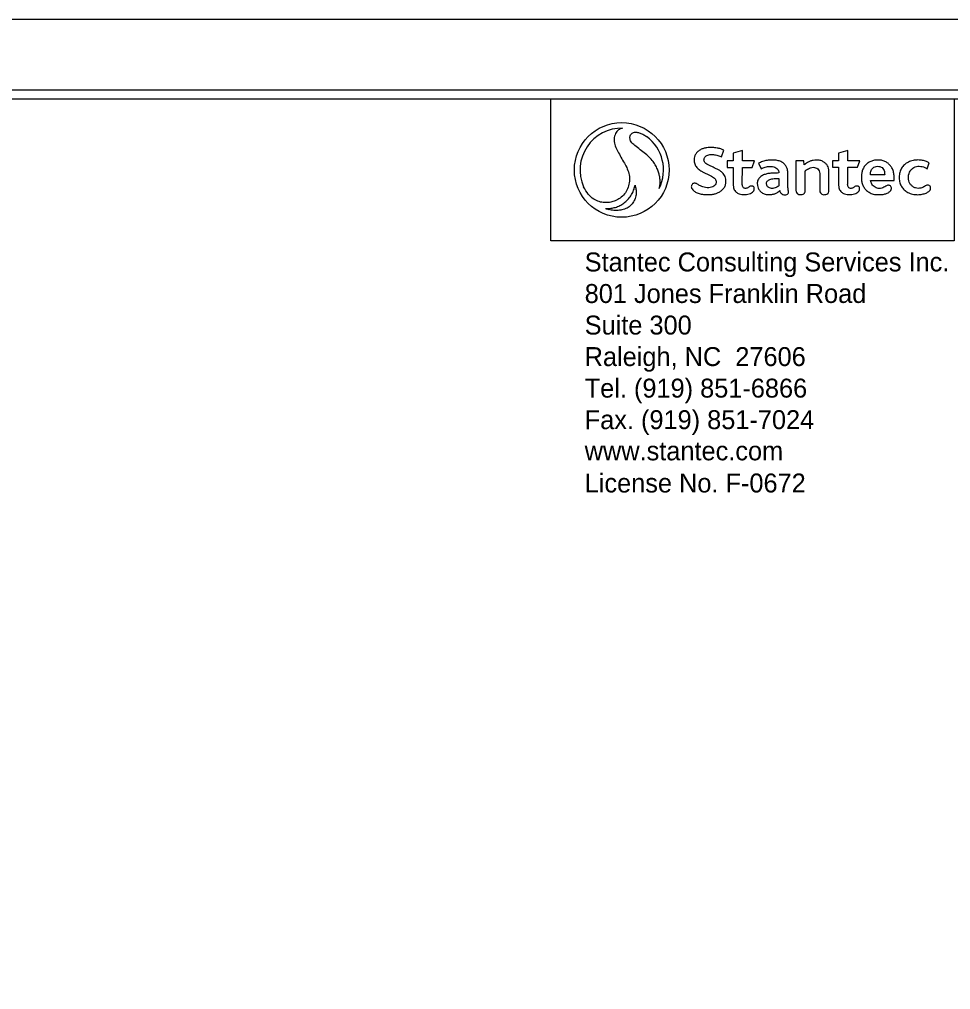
# Model space of a CAD drawing. Extents: x 2455709 to 2456046, y 594728 to 594947.
# Drawn here: x 2455949.3 to 2456001.9, y 594891.8 to 594946.6 of the extents above; entities that cross this region are included whole.
import ezdxf

# ---------------------------------------------------------------- set-up
doc = ezdxf.new("R2010")
doc.units = 0
for name, color, linetype in [('Prop Horizontal Alignment', 7, 'Continuous'), ('Prop Roadway Culvert', 7, 'Continuous'), ('Prop Vertical Profile Curve Label', 7, 'Continuous'), ('Prop Vertical Profile Grade', 7, 'Continuous'), ('Prop Vertical Profile Grade Label', 7, 'Continuous')]:
    doc.layers.add(name, color=color, linetype=linetype)

msp = doc.modelspace()

# ---------------------------------------------------------------- linework, layer by layer
at = {"layer": 'Prop Horizontal Alignment'}
msp.add_lwpolyline([(2456042.112, 594942.076), (2455742.104, 594942.076), (2455742.104, 594732.076), (2456042.107, 594732.076)], close=True, dxfattribs=at)
at = {"layer": 'Prop Roadway Culvert'}
msp.add_lwpolyline([(2455708.807, 594727.574), (2456045.507, 594727.574), (2456045.507, 594946.574), (2455708.807, 594946.574)], close=True, dxfattribs=at)
at = {"layer": 'Prop Vertical Profile Curve Label'}
msp.add_lwpolyline([(2455979.323, 594942.076), (2456002.097, 594942.079), (2456002.098, 594934.07), (2455979.324, 594934.067)], close=True, dxfattribs=at)
at = {"layer": 'Prop Vertical Profile Grade'}
msp.add_lwpolyline([(2455711.407, 594731.574), (2456044.604, 594731.576), (2456044.607, 594942.574), (2455711.407, 594942.574)], close=True, dxfattribs=at)
at = {"layer": 'Prop Vertical Profile Grade Label'}
for p, q in [((2455988.965, 594938.819), (2455989.095, 594939.192)), ((2455990.145, 594939.169), (2455989.619, 594939.022)), ((2455989.619, 594939.022), (2455989.619, 594938.585)), ((2455990.145, 594938.585), (2455990.145, 594939.169)), ((2455996.092, 594939.17), (2455995.566, 594939.023)), ((2455995.566, 594939.023), (2455995.566, 594938.586)), ((2455996.092, 594938.586), (2455996.092, 594939.17)), ((2455989.619, 594938.585), (2455989.285, 594938.585)), ((2455989.285, 594938.585), (2455989.285, 594938.219)), ((2455990.826, 594938.585), (2455990.145, 594938.585)), ((2455990.699, 594938.219), (2455990.826, 594938.585)), ((2455991.046, 594938.451), (2455991.206, 594938.141)), ((2455993.606, 594938.584), (2455993.163, 594938.584)), ((2455993.163, 594938.584), (2455993.163, 594936.906)), ((2455993.635, 594938.362), (2455993.606, 594938.584)), ((2455995.566, 594938.586), (2455995.231, 594938.586)), ((2455995.231, 594938.586), (2455995.231, 594938.22)), ((2455996.773, 594938.586), (2455996.092, 594938.586)), ((2455996.645, 594938.22), (2455996.773, 594938.586)), ((2456000.57, 594938.131), (2456000.686, 594938.475)), ((2455989.285, 594938.219), (2455989.623, 594938.219)), ((2455990.135, 594937.294), (2455990.142, 594938.219)), ((2455990.142, 594938.219), (2455990.699, 594938.219)), ((2455993.679, 594936.906), (2455993.679, 594938.014)), ((2455995.231, 594938.22), (2455995.57, 594938.22)), ((2455996.082, 594937.295), (2455996.089, 594938.22)), ((2455996.089, 594938.22), (2455996.645, 594938.22)), ((2455998.174, 594937.803), (2455997.371, 594937.803)), ((2455992.195, 594937.591), (2455992.196, 594937.176)), ((2455997.371, 594937.481), (2455998.707, 594937.481))]:
    msp.add_line(p, q, dxfattribs=at)
for points in [[(2455983.379, 594940.428), (2455983.379, 594940.428)], [(2455984.732, 594939.965), (2455984.732, 594939.965)]]:
    msp.add_lwpolyline(points, dxfattribs=at)
msp.add_circle((2455983.328, 594938.072), 2.673, dxfattribs=at)
for start, end in [(88.7738, 203.6916), (88.7673, 88.7738), (333.7886, 53.4398), (247.1256, 251.4651)]:
    msp.add_arc((2455983.328, 594938.072), 2.357, start, end, dxfattribs=at)
for points, degree in [([(2455983.379, 594940.428), (2455983.322, 594940.416), (2455983.188, 594940.388), (2455983.013, 594940.209), (2455982.883, 594939.916), (2455982.9, 594939.587), (2455983.016, 594939.269), (2455983.192, 594938.96), (2455983.374, 594938.619), (2455983.576, 594938.297), (2455983.716, 594937.97), (2455983.782, 594937.614), (2455983.739, 594937.258), (2455983.635, 594936.931), (2455983.434, 594936.634), (2455983.17, 594936.423), (2455982.894, 594936.299), (2455982.644, 594936.222), (2455982.365, 594936.222), (2455982.055, 594936.265), (2455981.749, 594936.405), (2455981.423, 594936.681), (2455981.266, 594936.952), (2455981.17, 594937.125)], 3), ([(2455983.379, 594940.428), (2455983.379, 594940.428), (2455983.379, 594940.428), (2455983.379, 594940.428)], 2), ([(2455985.442, 594937.031), (2455985.463, 594937.114), (2455985.498, 594937.269), (2455985.491, 594937.518), (2455985.467, 594937.737), (2455985.403, 594937.94), (2455985.327, 594938.175), (2455985.194, 594938.43), (2455985.004, 594938.67), (2455984.756, 594938.923), (2455984.446, 594939.148), (2455984.127, 594939.409), (2455983.871, 594939.601), (2455983.781, 594939.827), (2455983.78, 594939.999), (2455983.865, 594940.115), (2455983.978, 594940.196), (2455984.129, 594940.21), (2455984.307, 594940.176), (2455984.513, 594940.089), (2455984.655, 594940.009), (2455984.732, 594939.965)], 3), ([(2455989.095, 594939.192), (2455989.072, 594939.203), (2455988.968, 594939.253), (2455988.77, 594939.305), (2455988.527, 594939.335), (2455988.306, 594939.346), (2455988.121, 594939.328), (2455987.945, 594939.291), (2455987.775, 594939.224), (2455987.611, 594939.111), (2455987.493, 594938.961), (2455987.426, 594938.809), (2455987.411, 594938.667), (2455987.418, 594938.536), (2455987.446, 594938.411), (2455987.499, 594938.308), (2455987.563, 594938.215), (2455987.642, 594938.13), (2455987.738, 594938.053), (2455987.856, 594937.982), (2455988.003, 594937.906), (2455988.165, 594937.832), (2455988.33, 594937.762), (2455988.466, 594937.692), (2455988.566, 594937.607), (2455988.635, 594937.527), (2455988.659, 594937.429), (2455988.656, 594937.336), (2455988.618, 594937.233), (2455988.533, 594937.148), (2455988.398, 594937.09), (2455988.238, 594937.066), (2455988.06, 594937.074), (2455987.903, 594937.107), (2455987.776, 594937.17), (2455987.673, 594937.212), (2455987.604, 594937.277), (2455987.538, 594937.302), (2455987.478, 594937.328), (2455987.413, 594937.324), (2455987.348, 594937.304), (2455987.293, 594937.256), (2455987.257, 594937.188), (2455987.254, 594937.113), (2455987.265, 594937.039), (2455987.323, 594936.961), (2455987.435, 594936.849), (2455987.633, 594936.752), (2455987.878, 594936.687), (2455988.127, 594936.674), (2455988.341, 594936.68), (2455988.528, 594936.704), (2455988.692, 594936.754), (2455988.863, 594936.831), (2455989.027, 594936.96), (2455989.154, 594937.12), (2455989.208, 594937.309), (2455989.215, 594937.479), (2455989.194, 594937.633), (2455989.133, 594937.757), (2455989.06, 594937.881), (2455988.932, 594937.986), (2455988.787, 594938.083), (2455988.627, 594938.16), (2455988.454, 594938.241), (2455988.274, 594938.318), (2455988.121, 594938.399), (2455988.018, 594938.492), (2455987.974, 594938.583), (2455987.966, 594938.678), (2455987.994, 594938.765), (2455988.053, 594938.841), (2455988.135, 594938.895), (2455988.243, 594938.934), (2455988.372, 594938.944), (2455988.5, 594938.939), (2455988.627, 594938.919), (2455988.75, 594938.892), (2455988.865, 594938.858), (2455988.934, 594938.831), (2455988.965, 594938.819)], 3), ([(2455992.247, 594936.915), (2455992.248, 594936.897), (2455992.252, 594936.854), (2455992.295, 594936.79), (2455992.357, 594936.718), (2455992.469, 594936.666), (2455992.587, 594936.67), (2455992.697, 594936.694), (2455992.74, 594936.781), (2455992.742, 594936.868), (2455992.717, 594936.985), (2455992.69, 594937.307), (2455992.71, 594937.647), (2455992.704, 594938.015), (2455992.662, 594938.193), (2455992.562, 594938.353), (2455992.454, 594938.476), (2455992.276, 594938.566), (2455992.056, 594938.623), (2455991.795, 594938.64), (2455991.531, 594938.614), (2455991.277, 594938.555), (2455991.121, 594938.485), (2455991.046, 594938.451)], 3), ([(2455991.206, 594938.141), (2455991.23, 594938.154), (2455991.303, 594938.193), (2455991.422, 594938.23), (2455991.566, 594938.267), (2455991.702, 594938.276), (2455991.844, 594938.271), (2455991.972, 594938.231), (2455992.083, 594938.167), (2455992.161, 594938.074), (2455992.194, 594937.979), (2455992.194, 594937.92), (2455992.194, 594937.901)], 3), ([(2455993.679, 594938.014), (2455993.687, 594938.022), (2455993.723, 594938.055), (2455993.809, 594938.107), (2455993.921, 594938.181), (2455994.063, 594938.224), (2455994.207, 594938.223), (2455994.346, 594938.178), (2455994.441, 594938.079), (2455994.493, 594937.961), (2455994.52, 594937.801), (2455994.503, 594937.562), (2455994.515, 594937.259), (2455994.499, 594937.006), (2455994.51, 594936.832), (2455994.57, 594936.738), (2455994.675, 594936.672), (2455994.797, 594936.674), (2455994.913, 594936.702), (2455995.008, 594936.774), (2455995.035, 594936.912), (2455995.015, 594937.156), (2455995.028, 594937.456), (2455995.021, 594937.786), (2455995.033, 594937.996), (2455995.005, 594938.178), (2455994.948, 594938.306), (2455994.857, 594938.437), (2455994.711, 594938.54), (2455994.527, 594938.627), (2455994.317, 594938.632), (2455994.128, 594938.621), (2455993.958, 594938.565), (2455993.807, 594938.495), (2455993.706, 594938.415), (2455993.653, 594938.375), (2455993.635, 594938.362)], 3), ([(2455998.707, 594937.481), (2455998.709, 594937.532), (2455998.713, 594937.66), (2455998.69, 594937.866), (2455998.638, 594938.097), (2455998.527, 594938.275), (2455998.402, 594938.429), (2455998.243, 594938.538), (2455998.041, 594938.618), (2455997.815, 594938.633), (2455997.593, 594938.629), (2455997.382, 594938.562), (2455997.201, 594938.459), (2455997.044, 594938.309), (2455996.937, 594938.128), (2455996.877, 594937.929), (2455996.854, 594937.726), (2455996.851, 594937.507), (2455996.9, 594937.305), (2455996.98, 594937.108), (2455997.102, 594936.939), (2455997.288, 594936.805), (2455997.519, 594936.691), (2455997.788, 594936.677), (2455998.033, 594936.679), (2455998.241, 594936.724), (2455998.405, 594936.803), (2455998.524, 594936.907), (2455998.568, 594937.019), (2455998.548, 594937.11), (2455998.503, 594937.183), (2455998.431, 594937.203), (2455998.36, 594937.213), (2455998.278, 594937.187), (2455998.181, 594937.126), (2455998.07, 594937.059), (2455997.934, 594937.028), (2455997.808, 594937.025), (2455997.684, 594937.057), (2455997.581, 594937.128), (2455997.479, 594937.211), (2455997.419, 594937.323), (2455997.382, 594937.413), (2455997.374, 594937.464), (2455997.371, 594937.481)], 3), ([(2455997.371, 594937.803), (2455997.371, 594937.82), (2455997.371, 594937.861), (2455997.376, 594937.939), (2455997.402, 594938.04), (2455997.465, 594938.146), (2455997.562, 594938.231), (2455997.695, 594938.278), (2455997.837, 594938.282), (2455997.97, 594938.241), (2455998.083, 594938.169), (2455998.139, 594938.046), (2455998.167, 594937.922), (2455998.172, 594937.84), (2455998.174, 594937.803)], 3), ([(2456000.686, 594938.475), (2456000.642, 594938.5), (2456000.532, 594938.561), (2456000.319, 594938.617), (2456000.053, 594938.645), (2455999.77, 594938.612), (2455999.499, 594938.524), (2455999.276, 594938.374), (2455999.115, 594938.172), (2455999.015, 594937.938), (2455998.98, 594937.676), (2455999.001, 594937.411), (2455999.091, 594937.174), (2455999.225, 594936.992), (2455999.411, 594936.833), (2455999.666, 594936.714), (2455999.965, 594936.667), (2456000.239, 594936.685), (2456000.466, 594936.745), (2456000.645, 594936.827), (2456000.762, 594936.94), (2456000.768, 594937.047), (2456000.758, 594937.127), (2456000.704, 594937.176), (2456000.649, 594937.209), (2456000.588, 594937.213), (2456000.506, 594937.2), (2456000.433, 594937.136), (2456000.326, 594937.091), (2456000.22, 594937.041), (2456000.067, 594937.029), (2455999.908, 594937.043), (2455999.755, 594937.126), (2455999.64, 594937.242), (2455999.548, 594937.38), (2455999.52, 594937.544), (2455999.496, 594937.706), (2455999.542, 594937.866), (2455999.604, 594938.013), (2455999.695, 594938.13), (2455999.818, 594938.217), (2455999.958, 594938.272), (2456000.122, 594938.285), (2456000.286, 594938.27), (2456000.443, 594938.22), (2456000.529, 594938.16), (2456000.57, 594938.131)], 3), ([(2455989.623, 594938.219), (2455989.621, 594937.892), (2455989.62, 594937.547), (2455989.624, 594937.162), (2455989.641, 594937.07), (2455989.677, 594936.944), (2455989.749, 594936.858), (2455989.821, 594936.791), (2455989.898, 594936.74), (2455990.02, 594936.698), (2455990.188, 594936.679), (2455990.362, 594936.687), (2455990.536, 594936.711), (2455990.668, 594936.778), (2455990.765, 594936.856), (2455990.81, 594936.946), (2455990.815, 594937.025), (2455990.801, 594937.092), (2455990.766, 594937.131), (2455990.724, 594937.156), (2455990.675, 594937.165), (2455990.623, 594937.166), (2455990.57, 594937.152), (2455990.523, 594937.114), (2455990.47, 594937.074), (2455990.405, 594937.046), (2455990.336, 594937.024), (2455990.264, 594937.032), (2455990.202, 594937.066), (2455990.154, 594937.114), (2455990.133, 594937.197), (2455990.134, 594937.256), (2455990.135, 594937.294)], 3), ([(2455992.194, 594937.901), (2455992.16, 594937.9), (2455992.05, 594937.898), (2455991.859, 594937.889), (2455991.632, 594937.877), (2455991.42, 594937.83), (2455991.224, 594937.749), (2455991.053, 594937.602), (2455990.973, 594937.394), (2455990.984, 594937.198), (2455991.016, 594937.03), (2455991.118, 594936.888), (2455991.266, 594936.758), (2455991.478, 594936.679), (2455991.698, 594936.676), (2455991.902, 594936.702), (2455992.057, 594936.757), (2455992.172, 594936.835), (2455992.22, 594936.887), (2455992.247, 594936.915)], 3), ([(2455995.57, 594938.22), (2455995.568, 594937.892), (2455995.567, 594937.548), (2455995.57, 594937.163), (2455995.588, 594937.07), (2455995.624, 594936.944), (2455995.695, 594936.859), (2455995.768, 594936.792), (2455995.844, 594936.741), (2455995.967, 594936.698), (2455996.135, 594936.68), (2455996.309, 594936.687), (2455996.482, 594936.711), (2455996.614, 594936.778), (2455996.711, 594936.857), (2455996.757, 594936.947), (2455996.762, 594937.026), (2455996.747, 594937.092), (2455996.712, 594937.132), (2455996.671, 594937.156), (2455996.621, 594937.165), (2455996.569, 594937.166), (2455996.517, 594937.153), (2455996.47, 594937.115), (2455996.417, 594937.075), (2455996.351, 594937.047), (2455996.282, 594937.025), (2455996.211, 594937.033), (2455996.149, 594937.067), (2455996.1, 594937.115), (2455996.08, 594937.198), (2455996.081, 594937.257), (2455996.082, 594937.295)], 3), ([(2455982.412, 594935.901), (2455982.47, 594935.895), (2455982.606, 594935.882), (2455982.84, 594935.927), (2455983.101, 594935.988), (2455983.336, 594936.125), (2455983.552, 594936.277), (2455983.755, 594936.495), (2455983.923, 594936.737), (2455984.03, 594936.99), (2455984.062, 594937.139), (2455984.078, 594937.21)], 3), ([(2455984.078, 594937.21), (2455984.095, 594937.15), (2455984.139, 594936.997), (2455984.15, 594936.741), (2455984.106, 594936.463), (2455983.963, 594936.211), (2455983.771, 594935.979), (2455983.491, 594935.852), (2455983.194, 594935.784), (2455982.888, 594935.779), (2455982.679, 594935.819), (2455982.579, 594935.838)], 3), ([(2455992.196, 594937.176), (2455992.183, 594937.165), (2455992.134, 594937.128), (2455992.045, 594937.08), (2455991.92, 594937.028), (2455991.787, 594937.02), (2455991.672, 594937.05), (2455991.592, 594937.102), (2455991.54, 594937.163), (2455991.505, 594937.237), (2455991.5, 594937.316), (2455991.515, 594937.395), (2455991.562, 594937.47), (2455991.643, 594937.518), (2455991.739, 594937.561), (2455991.866, 594937.578), (2455991.996, 594937.585), (2455992.111, 594937.592), (2455992.171, 594937.591), (2455992.195, 594937.591)], 3), ([(2455993.163, 594936.906), (2455993.168, 594936.884), (2455993.179, 594936.834), (2455993.216, 594936.749), (2455993.31, 594936.677), (2455993.441, 594936.676), (2455993.573, 594936.686), (2455993.651, 594936.772), (2455993.679, 594936.847), (2455993.679, 594936.888), (2455993.679, 594936.906)], 3)]:
    msp.add_open_spline(points, degree=degree, dxfattribs=at)

# ---------------------------------------------------------------- texts
for s, height, p in [('Stantec Consulting Services Inc.', 1.06932, (2455981.236, 594932.34)), ('801 Jones Franklin Road', 1.06932, (2455981.236, 594930.559)), ('Suite 300', 1.0693, (2455981.236, 594928.777)), ('Raleigh, NC  27606', 1.06932, (2455981.236, 594926.996)), ('Tel. (919) 851-6866', 1.06932, (2455981.237, 594925.215)), ('Fax. (919) 851-7024', 1.06932, (2455981.237, 594923.433)), ('www.stantec.com', 1.06932, (2455981.237, 594921.673)), ('License No. F-0672', 1.06932, (2455981.237, 594919.857))]:
    msp.add_text(s, height=height, rotation=0.0071, dxfattribs=at).set_placement(p)

doc.saveas('drawing.dxf')
